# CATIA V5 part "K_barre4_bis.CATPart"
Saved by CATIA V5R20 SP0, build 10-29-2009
Part number: barre_4_bis
Bounding box of the stored display mesh (mm): x -16.009 to 2.493, y -12 to -11, z -8.999 to 2.493
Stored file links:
  G:\Khaled_CFAO_2011\ST2M\ST2M_GR2\gcausse\Khaled\CAD_ThinkMotion\K_barre4_bis.CATPart
  C:\Documents and Settings\gcausse\Bureau\video thinkmotio\assemblage_gcausse\pupitre_think.CATProduct
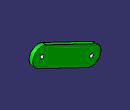
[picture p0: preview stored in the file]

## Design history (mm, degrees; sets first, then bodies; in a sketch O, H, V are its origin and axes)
Set1
  Sketch1 on Plane1, origin (0, -12, 0), H (-1, 0, 0), V (0, 0, 1)
    line L1 (1.0843, 2.2526) -> (14.6, -4.2533)
    arc A1 centre (13.5157, -6.5059) radius 2.5 from (14.6, -4.2533) to (12.4313, -8.7585) cw
    point P3 (13.5157, -6.5059)
    line L2 (12.4313, -8.7585) -> (-1.0843, -2.2526)
    arc A2 centre (0, 0) radius 2.5 from (-1.0843, -2.2526) to (1.0843, 2.2526) cw
    point P6 (0, 0)
    reference projected point E1 (0, 0) from Point1
    reference projected line E2 (0, 0) -> (13.5157, -6.5059) from Line1
    reference projected point E3 (13.5157, -6.5059) from Point2
    distance L2 L1 = 5
    tangency: A1 L1, L2 A1, A2 L1, A2 L2
    coincidence: P6 E1, P3 E3
    parallelism: L1 E2
Set2
  Plane1: linked copy from another document
  Point1: linked copy from another document
  Line1: linked copy from another document
  Point2: linked copy from another document
Body1 (main body)
  Pad1: profile Sketch1, direction (0, 1, 0), length 1
  Sketch2 on start face of Pad1, origin (-10.7261, -12, -4.0779), H (1, 0, 0), V (0, 0, 1)
    point P1 (-2.7896, -2.428)
    reference projected point E1 (-2.7896, -2.428) from Point2
    coincidence: P1 E1
  Hole1: placed by Sketch2, at (-13.5157, -12, -6.5059) direction (0, 1, 0), diameter 1, depth 1
  Sketch3 on start face of Pad1, origin (-1.88, -12, 0.4465), H (1, 0, 0), V (0, 0, 1)
    point P1 (1.88, -0.4465)
    reference projected point E1 (1.88, -0.4465) from Point1
    coincidence: P1 E1
  Hole2: placed by Sketch3, at (0, -12, 0) direction (0, 1, 0), diameter 1, depth 1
